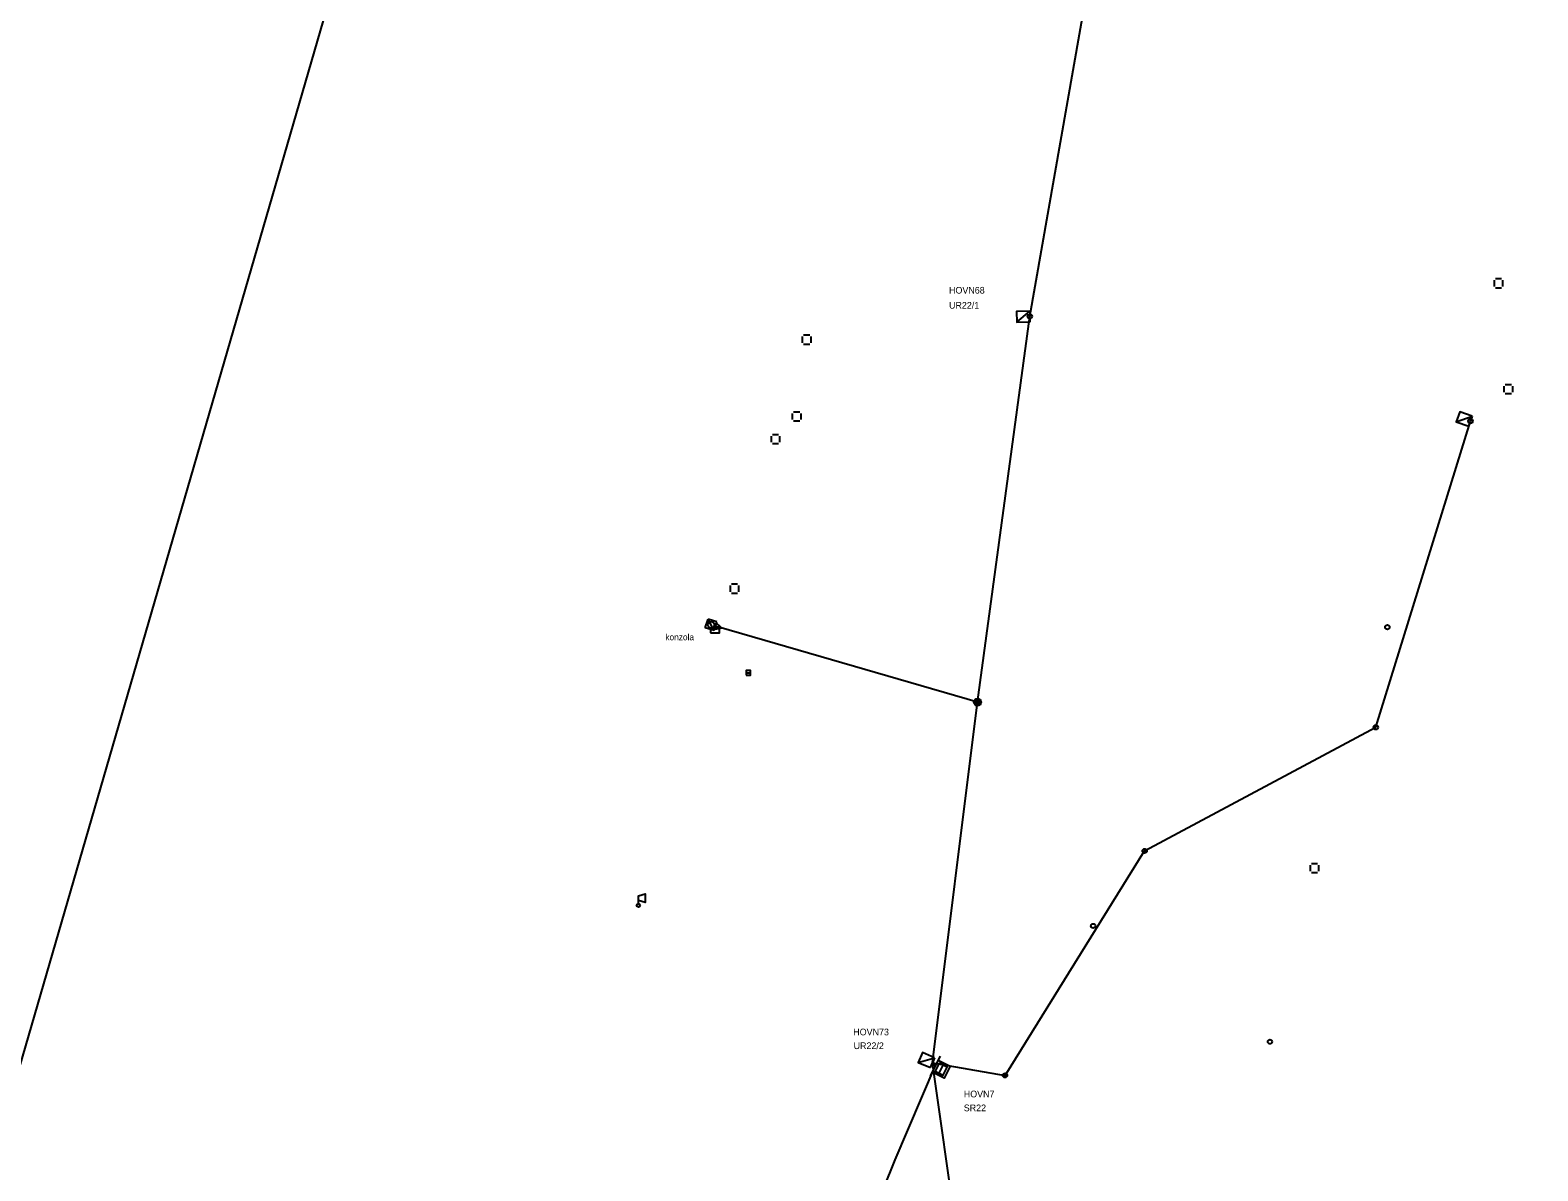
# Model space of a CAD drawing. Extents: x -575024 to -573705, y -1188419 to -1187266.
# Drawn here: x -574043.4 to -573873.7, y -1187924.4 to -1187796 of the extents above; entities that cross this region are included whole.
import ezdxf

# ---------------------------------------------------------------- set-up
doc = ezdxf.new("R2010")
doc.units = 0
for name, color, linetype in [('f002_inz_znacky_mimo_TO2', 7, 'Continuous'), ('f004_popisy_mts', 7, 'Continuous'), ('f004_rozvadec', 7, 'Continuous'), ('f005_nadz_ved_linie', 7, 'Continuous'), ('f005_nadz_ved_texty', 7, 'Continuous'), ('f005_nadz_ved_znacky', 7, 'Continuous'), ('f006_osa_trasy', 7, 'Continuous'), ('f317_zajmove_uzemi', 7, 'Continuous')]:
    doc.layers.add(name, color=color, linetype=linetype)

msp = doc.modelspace()

# ---------------------------------------------------------------- linework, layer by layer
at = {"layer": 'f002_inz_znacky_mimo_TO2'}
for p, q in [((-573878.63, -1187824.17), (-573878.63, -1187824.87)), ((-573877.78, -1187824.02), (-573878.48, -1187824.02)), ((-573878.48, -1187825.02), (-573877.78, -1187825.02)), ((-573877.63, -1187824.87), (-573877.63, -1187824.17)), ((-573956.51, -1187830.5), (-573956.51, -1187831.2)), ((-573955.66, -1187830.35), (-573956.36, -1187830.35)), ((-573955.51, -1187831.2), (-573955.51, -1187830.5)), ((-573956.36, -1187831.35), (-573955.66, -1187831.35)), ((-573877.51, -1187836.07), (-573877.51, -1187836.77)), ((-573876.66, -1187835.92), (-573877.36, -1187835.92)), ((-573877.36, -1187836.92), (-573876.66, -1187836.92)), ((-573876.51, -1187836.77), (-573876.51, -1187836.07)), ((-573957.63, -1187839.15), (-573957.63, -1187839.85)), ((-573956.78, -1187839), (-573957.48, -1187839)), ((-573956.63, -1187839.85), (-573956.63, -1187839.15)), ((-573957.48, -1187840), (-573956.78, -1187840)), ((-573960.02, -1187841.7), (-573960.02, -1187842.4)), ((-573959.17, -1187841.55), (-573959.87, -1187841.55)), ((-573959.87, -1187842.55), (-573959.17, -1187842.55)), ((-573959.02, -1187842.4), (-573959.02, -1187841.7)), ((-573964.63, -1187858.52), (-573964.63, -1187859.22)), ((-573963.78, -1187858.37), (-573964.48, -1187858.37)), ((-573964.48, -1187859.37), (-573963.78, -1187859.37)), ((-573963.63, -1187859.22), (-573963.63, -1187858.52)), ((-573962.81, -1187868.35), (-573962.31, -1187868.35)), ((-573899.34, -1187889.98), (-573899.34, -1187890.68)), ((-573898.49, -1187889.83), (-573899.19, -1187889.83)), ((-573898.34, -1187890.68), (-573898.34, -1187889.98)), ((-573899.19, -1187890.83), (-573898.49, -1187890.83))]:
    msp.add_line(p, q, dxfattribs=at)
for points in [[(-573966.82, -1187863.85), (-573965.82, -1187863.85), (-573965.82, -1187863.35), (-573966.82, -1187863.35)], [(-573962.81, -1187868.6), (-573962.31, -1187868.6), (-573962.31, -1187868.1), (-573962.81, -1187868.1)]]:
    msp.add_lwpolyline(points, close=True, dxfattribs=at)
msp.add_lwpolyline([(-573974.95, -1187894.51), (-573974.95, -1187893.46), (-573974.2, -1187893.21), (-573974.2, -1187894.21), (-573974.95, -1187893.96)], dxfattribs=at)
for centre, radius in [((-573881.28, -1187840.03), 0.25), ((-573890.64, -1187863.21), 0.25), ((-573891.94, -1187874.48), 0.25), ((-573917.96, -1187888.39), 0.25), ((-573974.95, -1187894.51), 0.2), ((-573923.76, -1187896.83), 0.25), ((-573903.86, -1187909.86), 0.25)]:
    msp.add_circle(centre, radius, dxfattribs=at)
at = {"layer": 'f004_rozvadec'}
for p, q in [((-573932.36, -1187828.9), (-573930.9, -1187827.64)), ((-573930.9, -1187827.64), (-573930.88, -1187828.24)), ((-573930.86, -1187828.84), (-573930.88, -1187828.24)), ((-573882.89, -1187840.11), (-573881.09, -1187839.46)), ((-573881.47, -1187840.6), (-573881.28, -1187840.03)), ((-573881.09, -1187839.46), (-573881.28, -1187840.03)), ((-573967.42, -1187863.28), (-573967.11, -1187862.29)), ((-573966.11, -1187862.6), (-573967.11, -1187862.29)), ((-573966.54, -1187863.39), (-573967.02, -1187862.46)), ((-573966.43, -1187863.6), (-573966.11, -1187862.6)), ((-573966.43, -1187863.6), (-573967.42, -1187863.28)), ((-573943.46, -1187912.18), (-573941.6, -1187911.67)), ((-573940.97, -1187911.49), (-573942.11, -1187913.71)), ((-573941.6, -1187911.67), (-573941.84, -1187912.22)), ((-573942.08, -1187912.77), (-573941.84, -1187912.22))]:
    msp.add_line(p, q, dxfattribs=at)
for points in [[(-573930.9, -1187827.64), (-573932.4, -1187827.7), (-573932.36, -1187828.9), (-573930.86, -1187828.84)], [(-573881.09, -1187839.46), (-573882.5, -1187838.98), (-573882.89, -1187840.11), (-573881.47, -1187840.6)], [(-573941.6, -1187911.67), (-573942.98, -1187911.08), (-573943.46, -1187912.18), (-573942.08, -1187912.77)], [(-573941.2, -1187911.93), (-573939.86, -1187912.61), (-573940.54, -1187913.95), (-573941.88, -1187913.27)], [(-573941.1, -1187913.39), (-573940.65, -1187913.61), (-573940.2, -1187912.72), (-573940.64, -1187912.49)]]:
    msp.add_lwpolyline(points, dxfattribs=at)
msp.add_lwpolyline([(-573941.09, -1187912.27), (-573941.54, -1187913.16), (-573941.1, -1187913.39), (-573940.64, -1187912.49)], close=True, dxfattribs=at)
msp.add_circle((-573966.77, -1187862.94), 0.369, dxfattribs=at)
at = {"layer": 'f005_nadz_ved_linie'}
for p, q in [((-573936.77, -1187871.65), (-573930.88, -1187828.24)), ((-573941.84, -1187912.22), (-573936.77, -1187871.65))]:
    msp.add_line(p, q, dxfattribs=at)
for points in [[(-573930.88, -1187828.24), (-573923.15, -1187784.3), (-573892.1, -1187691.22)], [(-573941.84, -1187912.22), (-573933.68, -1187913.65), (-573917.96, -1187888.39), (-573891.94, -1187874.48), (-573881.28, -1187840.03)], [(-573936.77, -1187871.65), (-573965.9, -1187863.21), (-573966.27, -1187863.1)], [(-574042.04, -1188033.33), (-574028.04, -1188036.36), (-573983.17, -1188026.95), (-573953.26, -1187968.86), (-573946.82, -1187947.17), (-573939.17, -1187930.9), (-573941.84, -1187912.22)]]:
    msp.add_lwpolyline(points, dxfattribs=at)
at = {"layer": 'f005_nadz_ved_znacky'}
for p, q in [((-573966.16, -1187862.75), (-573965.83, -1187863.05)), ((-573965.92, -1187863.39), (-573966.36, -1187863.47)), ((-573936.77, -1187871.25), (-573936.77, -1187872.05)), ((-573937.17, -1187871.65), (-573936.37, -1187871.65))]:
    msp.add_line(p, q, dxfattribs=at)
msp.add_lwpolyline([(-573965.83, -1187863.05), (-573965.54, -1187863.31), (-573965.92, -1187863.39)], close=True, dxfattribs=at)
for centre, radius in [((-573930.88, -1187828.24), 0.25), ((-573936.77, -1187871.65), 0.4), ((-573936.77, -1187871.65), 0.25), ((-573933.68, -1187913.65), 0.25)]:
    msp.add_circle(centre, radius, dxfattribs=at)
at = {"layer": 'f006_osa_trasy'}
msp.add_line((-573941.54, -1187912.6), (-573941.84, -1187912.22), dxfattribs=at)
msp.add_lwpolyline([(-573958.08, -1187942.27), (-573956.88, -1187937.4), (-573955.66, -1187931.85), (-573949.97, -1187932.94), (-573946.06, -1187923.16), (-573941.54, -1187912.6)], dxfattribs=at)
at = {"layer": 'f317_zajmove_uzemi'}
msp.add_lwpolyline([(-575015.94, -1188159.64), (-575023.56, -1188317.12), (-574520.64, -1188256.16), (-574408.88, -1188098.68), (-574246.32, -1188035.18), (-574167.58, -1188070.74), (-574025.34, -1188139.32), (-573890.72, -1188065.66), (-573763.72, -1187771.02), (-573705.3, -1187458.6), (-573768.8, -1187265.56), (-573961.84, -1187293.5), (-573895.8, -1187400.18), (-574050.74, -1187933.58), (-574152.34, -1187854.84), (-574464.76, -1187938.66), (-574579.06, -1188111.38)], close=True, dxfattribs=at)

# ---------------------------------------------------------------- texts
at = {"layer": 'f004_popisy_mts'}
for s, p in [('HOVN68', (-573939.98, -1187825.67)), ('UR22/1', (-573939.98, -1187827.36)), ('HOVN73', (-573950.76, -1187909.14)), ('UR22/2', (-573950.72, -1187910.69)), ('HOVN7', (-573938.32, -1187916.12)), ('SR22', (-573938.32, -1187917.68))]:
    msp.add_text(s, height=0.75, dxfattribs=at).set_placement(p)
at = {"layer": 'f005_nadz_ved_texty'}
msp.add_text('konzola', height=0.7, dxfattribs=at).set_placement((-573971.91, -1187864.68))

doc.saveas('drawing.dxf')
